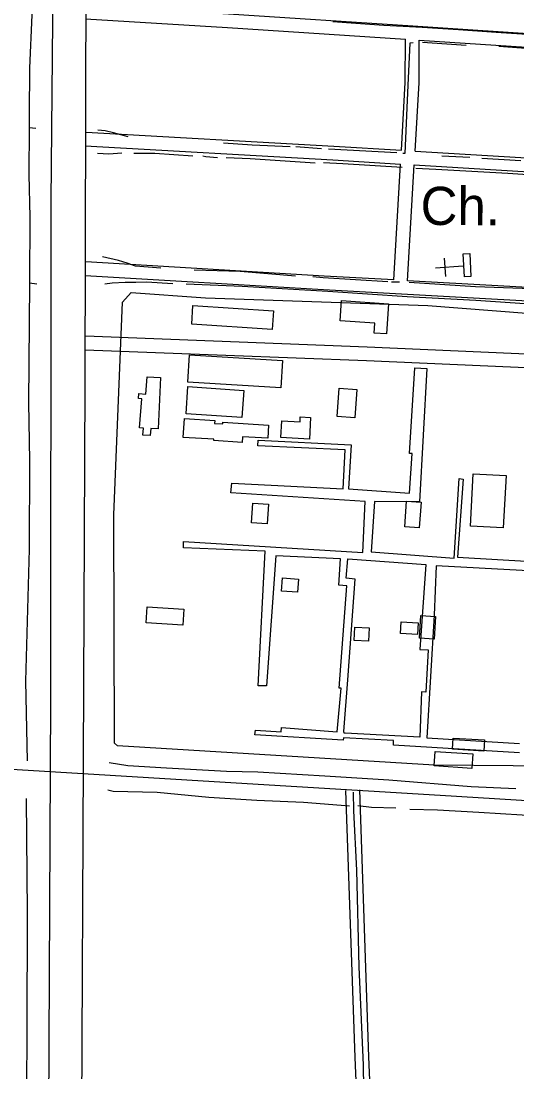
# Model space of a CAD drawing. Extents: x 3313447 to 3351316, y 703786 to 729172.
# Drawn here: x 3319138 to 3320216, y 717443 to 719729 of the extents above; entities that cross this region are included whole.
import ezdxf

# ---------------------------------------------------------------- set-up
doc = ezdxf.new("R2010")
doc.units = 0
for name, color, linetype in [('V-BLDG-OTLN', 7, 'Continuous'), ('V-DTCH-CNTR', 7, 'Continuous'), ('V-ROAD-CNTR', 7, 'Continuous'), ('V-SITE-OTLN', 7, 'Continuous'), ('V-SITE-OTLN-IDEN', 7, 'Continuous'), ('V-TOPO-SHOR', 7, 'Continuous'), ('V-UTIL-LINE', 7, 'Continuous')]:
    doc.layers.add(name, color=color, linetype=linetype)

msp = doc.modelspace()

# ---------------------------------------------------------------- linework, layer by layer
at = {"layer": 'V-BLDG-OTLN'}
for points in [[(3320102.2, 719172.1), (3320099.6, 719222), (3320113.6, 719222.7), (3320116.2, 719172.8)], [(3319834.9, 719120.4), (3319937, 719113.6), (3319932.7, 719048.2), (3319905.8, 719050), (3319907.2, 719071.4), (3319832, 719076.4)], [(3319511.9, 719110), (3319687, 719098.6), (3319684.3, 719057.6), (3319509.2, 719069)], [(3319504.6, 719002.7), (3319706.4, 718990.3), (3319702.7, 718930.7), (3319500.9, 718943.1)], [(3319435.9, 718841.4), (3319420.3, 718842.5), (3319419.1, 718826.9), (3319403.1, 718828.1), (3319404.2, 718843.3), (3319395.6, 718844), (3319400.3, 718906.8), (3319393.4, 718907.3), (3319394.2, 718918.1), (3319409.6, 718917), (3319412.4, 718954.7), (3319441.5, 718953.3)], [(3319500.9, 718933.5), (3319622.2, 718925.3), (3319618.2, 718866.3), (3319496.9, 718874.5)], [(3319825.2, 718868.7), (3319829.7, 718929.8), (3319868.4, 718926.9), (3319863.9, 718865.8)], [(3319493.2, 718864.1), (3319559.3, 718859.9), (3319558.9, 718853.5), (3319576.8, 718852.4), (3319577.1, 718855.9), (3319676.1, 718849.7), (3319674.4, 718821.1), (3319619.7, 718824.5), (3319618.9, 718812), (3319557.1, 718815.9), (3319557.2, 718818.9), (3319490.6, 718823.1)], [(3319765.5, 718819.4), (3319703, 718822.6), (3319704.9, 718858.7), (3319744.6, 718856.7), (3319745.1, 718867.8), (3319767.5, 718866.6)], [(3320192.8, 718739.9), (3320186.5, 718625.9), (3320114.9, 718629.9), (3320121.2, 718743.9)], [(3319676.1, 718677.6), (3319673.1, 718634.6), (3319638.8, 718637), (3319641.8, 718680)], [(3320008, 718682.3), (3320003.9, 718626.2), (3319972.3, 718628.5), (3319976.3, 718684.6)], [(3319706.7, 718517.5), (3319741.1, 718514.9), (3319739, 718486.3), (3319704.6, 718488.8)], [(3319411.9, 718454.3), (3319492, 718449.6), (3319489.9, 718414.6), (3319409.8, 718419.3)], [(3320039, 718433.7), (3320035.9, 718384.2), (3320004.3, 718386.2), (3320007.4, 718435.6)], [(3319863.8, 718410.3), (3319895.1, 718408.7), (3319893.6, 718379.6), (3319862.3, 718381.2)], [(3319999.9, 718393.9), (3319963.2, 718396.2), (3319964.8, 718422), (3320001.5, 718419.7)], [(3320077.7, 718168.6), (3320145.9, 718164.8), (3320144.5, 718140.6), (3320076.3, 718144.5)], [(3320038.7, 718140), (3320120.6, 718134.4), (3320118.5, 718103), (3320036.6, 718108.6)]]:
    msp.add_lwpolyline(points, close=True, dxfattribs=at)
at = {"layer": 'V-DTCH-CNTR'}
msp.add_lwpolyline([(3319860.5, 718051.1), (3319860.8, 718010.8), (3319867.1, 717881.4), (3319872.7, 717671.4), (3319882.2, 717457.4), (3319884.6, 717258.6), (3319894.6, 717014.3), (3319911.2, 716767.9), (3319920.4, 716508.3), (3319927.5, 716409.9), (3319932.4, 716361), (3319934.8, 716322), (3319935.4, 716240.2), (3319936.2, 716086.3), (3319933.4, 716059.3), (3319927.9, 716034.9), (3319902.2, 715961.8), (3319844.4, 715824.9), (3319840.3, 715815.1), (3319830.2, 715785.1)], dxfattribs=at)
at = {"layer": 'V-ROAD-CNTR'}
for points in [[(3319275.4, 715676.8), (3319267.4, 716170.4), (3319269, 717056.8), (3319273.1, 717958.7), (3319277.8, 718937.7), (3319279.3, 719833), (3319276.1, 720458.7), (3319279.4, 721216), (3319279.5, 721926.3), (3319286.5, 722373.9), (3319289, 723220.5), (3319295.3, 724050.7), (3319298.1, 724572.1)], [(3319225.7, 724387.2), (3319219.9, 723260.5), (3319216.9, 722089), (3319220.7, 721173.5), (3319213.5, 720516.4), (3319203, 719335.9), (3319201.9, 718251.3), (3319198, 717354.7), (3319193.3, 716367.9), (3319200.9, 715645.2)], [(3319278.2, 719733.6), (3319586.9, 719714.4), (3319974, 719689)], [(3319540.5, 719747.4), (3319588.8, 719744.4), (3319990, 719718), (3320305.8, 719697.2), (3321155.9, 719646.3), (3321918.1, 719601.2), (3321941.5, 719587.8), (3321949.6, 719568.6), (3321954.3, 719544.9), (3321945.9, 719327.2), (3321936.1, 719302.8)], [(3319964.9, 719447.5), (3319973.5, 719594.9), (3319974, 719689)], [(3319994.8, 719445.7), (3320003.5, 719593.9), (3320003.9, 719687)], [(3320003.9, 719687), (3320303.9, 719667.2), (3320622, 719648.2)], [(3319279.5, 719487), (3319817.8, 719456.4), (3319964.9, 719447.5)], [(3319277.8, 719457.1), (3319816, 719426.5), (3319963.1, 719417.6)], [(3319994.8, 719445.7), (3320611.7, 719408.5)], [(3319948.3, 719165.4), (3319963.1, 719417.6)], [(3319978.2, 719163.7), (3319993, 719415.8)], [(3319993, 719415.8), (3320610.4, 719378.5)], [(3319948.3, 719165.4), (3319797.3, 719173.8), (3319279.1, 719204.6)], [(3322281.5, 719005.5), (3321924.1, 719019.9), (3321491.7, 719045.1), (3321111.4, 719067.4), (3320566, 719101.1), (3319795.6, 719143.8), (3319277.3, 719174.7)], [(3320599.7, 719129.1), (3320567.8, 719131), (3319978.2, 719163.7)], [(3319278.5, 719043.8), (3319890.3, 719020), (3320335.7, 719000.5), (3321112.6, 718961.3), (3321956.6, 718916.9), (3322094.7, 718900)], [(3319277.3, 719013.8), (3319889.1, 718990), (3320334.3, 718970.5), (3321111.1, 718931.3), (3321953.9, 718887), (3322091.1, 718870.2)], [(3320627.7, 718008.6), (3320049.5, 718044.1), (3319581.5, 718072.4), (3319021.7, 718106.6), (3318048.4, 718163.1), (3317583.9, 718192.4)], [(3319843.8, 718055.2), (3319863.8, 717474.1), (3319892.6, 716796.3), (3319896.5, 716633), (3319908, 716320.9), (3319908, 716199.1), (3319905.8, 716136.1), (3319902.2, 716064.8), (3319896.2, 716025.7), (3319886.6, 715994.2), (3319858.9, 715928.1), (3319829.6, 715868.6), (3319805.7, 715807)], [(3319873.8, 718056.2), (3319893.8, 717475.3), (3319922.6, 716797.3), (3319926.5, 716633.9), (3319938, 716321.4), (3319938, 716198.6), (3319935.8, 716134.8), (3319932, 716061.8), (3319925.5, 716019), (3319914.8, 715984), (3319886.2, 715915.7), (3319857.1, 715856.5), (3319837.5, 715806.1)]]:
    msp.add_lwpolyline(points, dxfattribs=at)
at = {"layer": 'V-SITE-OTLN'}
for p, q in [((3320057.8, 719212.6), (3320060.6, 719172.7)), ((3320099.1, 719195.5), (3320039.2, 719191.2))]:
    msp.add_line(p, q, dxfattribs=at)
msp.add_lwpolyline([(3320380, 718107.3), (3320036.3, 718110), (3319348.1, 718151.8), (3319341, 718158), (3319339.8, 718654.8), (3319358.7, 719117.1), (3319377.1, 719138.2), (3319539.2, 719126.8), (3320022.8, 719109.9), (3320806.1, 719049)], dxfattribs=at)
at = {"layer": 'V-TOPO-SHOR'}
for p, q in [((3320105.8, 719675.6), (3320011.1, 719681.9)), ((3319170.4, 719494.7), (3319155.7, 719496.1)), ((3319791.1, 719450.9), (3319735.3, 719455.1)), ((3319955.3, 719442.3), (3319806.8, 719450.2)), ((3320113.9, 719431.7), (3320053.2, 719434.6)), ((3320224.5, 719424.5), (3320139.8, 719429.8)), ((3319172.1, 719156.3), (3319156.4, 719158.5)), ((3319961.2, 719160.8), (3319943.8, 719161))]:
    msp.add_line(p, q, dxfattribs=at)
for points in [[(3319158.3, 719888.4), (3319157.7, 719819.3), (3319161.2, 719742.2), (3319156.7, 719626), (3319155.9, 719525.2), (3319155.7, 719496.1), (3319155, 719394.7), (3319156.9, 719301.8)], [(3320249.3, 719698.4), (3320171.2, 719703.8), (3320089.2, 719709.3), (3320010.3, 719714.3), (3319926.9, 719718.8), (3319865.9, 719723.4), (3319815.6, 719726.7)], [(3319990.6, 719681.3), (3319983.6, 719680.6), (3319979.2, 719589.4), (3319972.7, 719440.2), (3319968.2, 719440.2)], [(3320629.5, 719644.9), (3320625, 719645), (3320454.2, 719655.6), (3320265.5, 719667), (3320176.6, 719673.3)], [(3319370.9, 719476.5), (3319339.3, 719485.4), (3319320.9, 719489.6), (3319304.8, 719491)], [(3319723, 719455.2), (3319640.3, 719458.8), (3319577.9, 719463)], [(3319357.2, 719441.1), (3319329.2, 719439.2), (3319304, 719440.6)], [(3319511.8, 719434.6), (3319428.7, 719440.3), (3319383, 719440.4)], [(3319564.9, 719431), (3319539.7, 719433.2), (3319533.6, 719434.5)], [(3319777.4, 719419.6), (3319636.4, 719428.8), (3319584, 719431)], [(3319966.8, 719410.2), (3319838, 719418.1), (3319795.8, 719420.2)], [(3320295.1, 719390.3), (3320196.3, 719396.7), (3320039.7, 719406), (3319996.7, 719408.1)], [(3319156.9, 719301.8), (3319156.4, 719161.3), (3319156.4, 719158.5), (3319154.4, 718898.5), (3319156.1, 718772.9), (3319155.9, 718580), (3319147.6, 718292.4), (3319151, 718119.7)], [(3319441.9, 719191), (3319387.2, 719195.7), (3319369.1, 719201.9), (3319349.7, 719208.1), (3319315.3, 719215.5)], [(3319734.7, 719174), (3319614.3, 719183.8), (3319514.2, 719187.1)], [(3319468.4, 719157.3), (3319410.5, 719160.5), (3319387.6, 719160), (3319364.1, 719159.6), (3319335.8, 719158.4), (3319320.2, 719156.5)], [(3319935.7, 719161.7), (3319794.9, 719170.3), (3319772.2, 719172.4)], [(3320406.9, 719136.6), (3320288.7, 719144.9), (3320126.1, 719150.2), (3319982, 719160)], [(3320127, 719120.7), (3319977.2, 719128.6), (3319805.3, 719140), (3319618.5, 719150.9), (3319497.2, 719156.4)], [(3322259.3, 718884.1), (3322258.2, 718976.3), (3322257, 718987.1), (3322253.7, 718991.8), (3322251, 718993.2), (3322247, 718993.9), (3322142.2, 719001.4), (3322040.7, 719006.2), (3322013.9, 719008.5), (3321890.9, 719014.8), (3321779.4, 719021.1), (3321641.1, 719030.9), (3321501.3, 719037.3), (3321345.5, 719046.6), (3321185.6, 719056.6), (3320998.9, 719066.8), (3320816.9, 719077.6), (3320662.4, 719087.6), (3320542.1, 719094.6), (3320430.6, 719102.2), (3320276.1, 719110.8), (3320127, 719120.7)], [(3320213.7, 718058.4), (3320116.7, 718063), (3319937.4, 718077.1), (3319798.4, 718086.3), (3319652.6, 718094.8), (3319584.7, 718096), (3319454.4, 718103.8), (3319370.4, 718108.5), (3319329.8, 718114.9)], [(3319149.4, 718037.8), (3319151.5, 717788.5), (3319150.8, 717531.1), (3319149.5, 717279.1), (3319151.3, 717225.9)], [(3319852.1, 718021), (3319752.4, 718028.6), (3319650.9, 718033.4), (3319546.2, 718039.6), (3319434, 718050.6), (3319338.6, 718052.7), (3319326.7, 718055.9)], [(3319952.6, 718016.8), (3319900.1, 718018), (3319870.2, 718021.5)], [(3321254.5, 717839.7), (3321198.6, 717855.3), (3321130.9, 717874), (3321066.5, 717892), (3320935.7, 717931.3), (3320837.8, 717956.9), (3320776.1, 717968.2), (3320657.9, 717975.8), (3320552.4, 717983.4), (3320374.4, 717990.8), (3320227.3, 718001.4), (3320133.3, 718006.8), (3320043.2, 718012.2), (3319983.4, 718013.9)]]:
    msp.add_lwpolyline(points, dxfattribs=at)
at = {"layer": 'V-UTIL-LINE'}
for points in [[(3320222, 718136.9), (3319948, 718153.8), (3319948, 718163.9), (3319838.8, 718169.4), (3319838.1, 718164.1), (3319646.5, 718176.3), (3319648, 718186.3), (3319703.5, 718182.5), (3319704.3, 718191.9), (3319825.5, 718182.3), (3319834.3, 718277.4), (3319829.6, 718277.4), (3319846.1, 718499.8), (3319828.7, 718501.9), (3319832.5, 718558.9), (3319691.8, 718565.3), (3319671.5, 718282.7), (3319653.4, 718282.8), (3319669.1, 718575.6), (3319490.9, 718583), (3319491.6, 718596.4), (3319880.9, 718572.6), (3319886.4, 718683.8), (3319594.3, 718702.2), (3319596.5, 718723.6), (3319838.4, 718711), (3319842.4, 718796.1), (3319652.8, 718804.3), (3319653.5, 718817), (3319855.9, 718806.7), (3319849.8, 718710.9), (3319982.4, 718701.8), (3319988.5, 718788.2), (3319982.4, 718788.3), (3319993.9, 718974.5), (3320020.1, 718973), (3320004.4, 718682.9), (3319906.5, 718683.6), (3319899.6, 718574.4), (3320079.8, 718560.3), (3320090.6, 718733.8), (3320099.3, 718732.4), (3320087.2, 718562.3), (3320323, 718549)], [(3319839.9, 718182.9), (3319848.8, 718295.5), (3319864.6, 718514.5), (3319845.2, 718516.7), (3319848.2, 718558.9), (3320018.4, 718546.8), (3320004.8, 718361.3), (3320022.9, 718361.1), (3320018.2, 718268.7), (3320008.8, 718269.4), (3320005.4, 718170.9), (3319842.6, 718179.6)], [(3320320.9, 718528.3), (3320040.8, 718543.8), (3320036.6, 718436), (3320020.5, 718169.3), (3320222.1, 718157)], [(3319842.6, 718179.6), (3319840.6, 718179.6), (3319839.9, 718182.9)]]:
    msp.add_lwpolyline(points, dxfattribs=at)

# ---------------------------------------------------------------- texts
at = {"layer": 'V-SITE-OTLN-IDEN'}
msp.add_text('Ch.', height=83, rotation=359.6345, dxfattribs=at).set_placement((3320006.5, 719285.3))

doc.saveas('drawing.dxf')
